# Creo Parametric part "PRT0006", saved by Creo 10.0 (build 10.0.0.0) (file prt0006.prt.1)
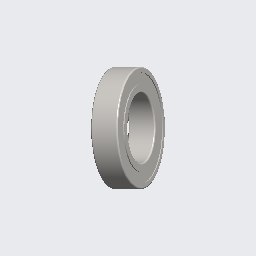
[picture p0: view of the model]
Units: millimeter Newton Second (mmNs); MM, TONNE, SECS

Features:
  1. coordinate system "KUGELLAGER"
  2. imported feature "Import-ke ID 4"

Other named items: NOTE_0

Notes: SS-61801-ZZ-MAE

Surfaces: 16 torus, 12 cylinder, 6 plane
